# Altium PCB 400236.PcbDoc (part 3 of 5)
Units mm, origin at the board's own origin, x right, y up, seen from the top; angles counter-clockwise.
Board outline 136.53 x 63.5 mm, 4 copper layers (Top Layer, Mid-Layer 1, Mid-Layer 2, Bottom Layer), stack 1.49 mm thick; 344 components, 236 nets, 1364 pads, 1393 vias.
Unrouted connection lines stored in the file: 6.
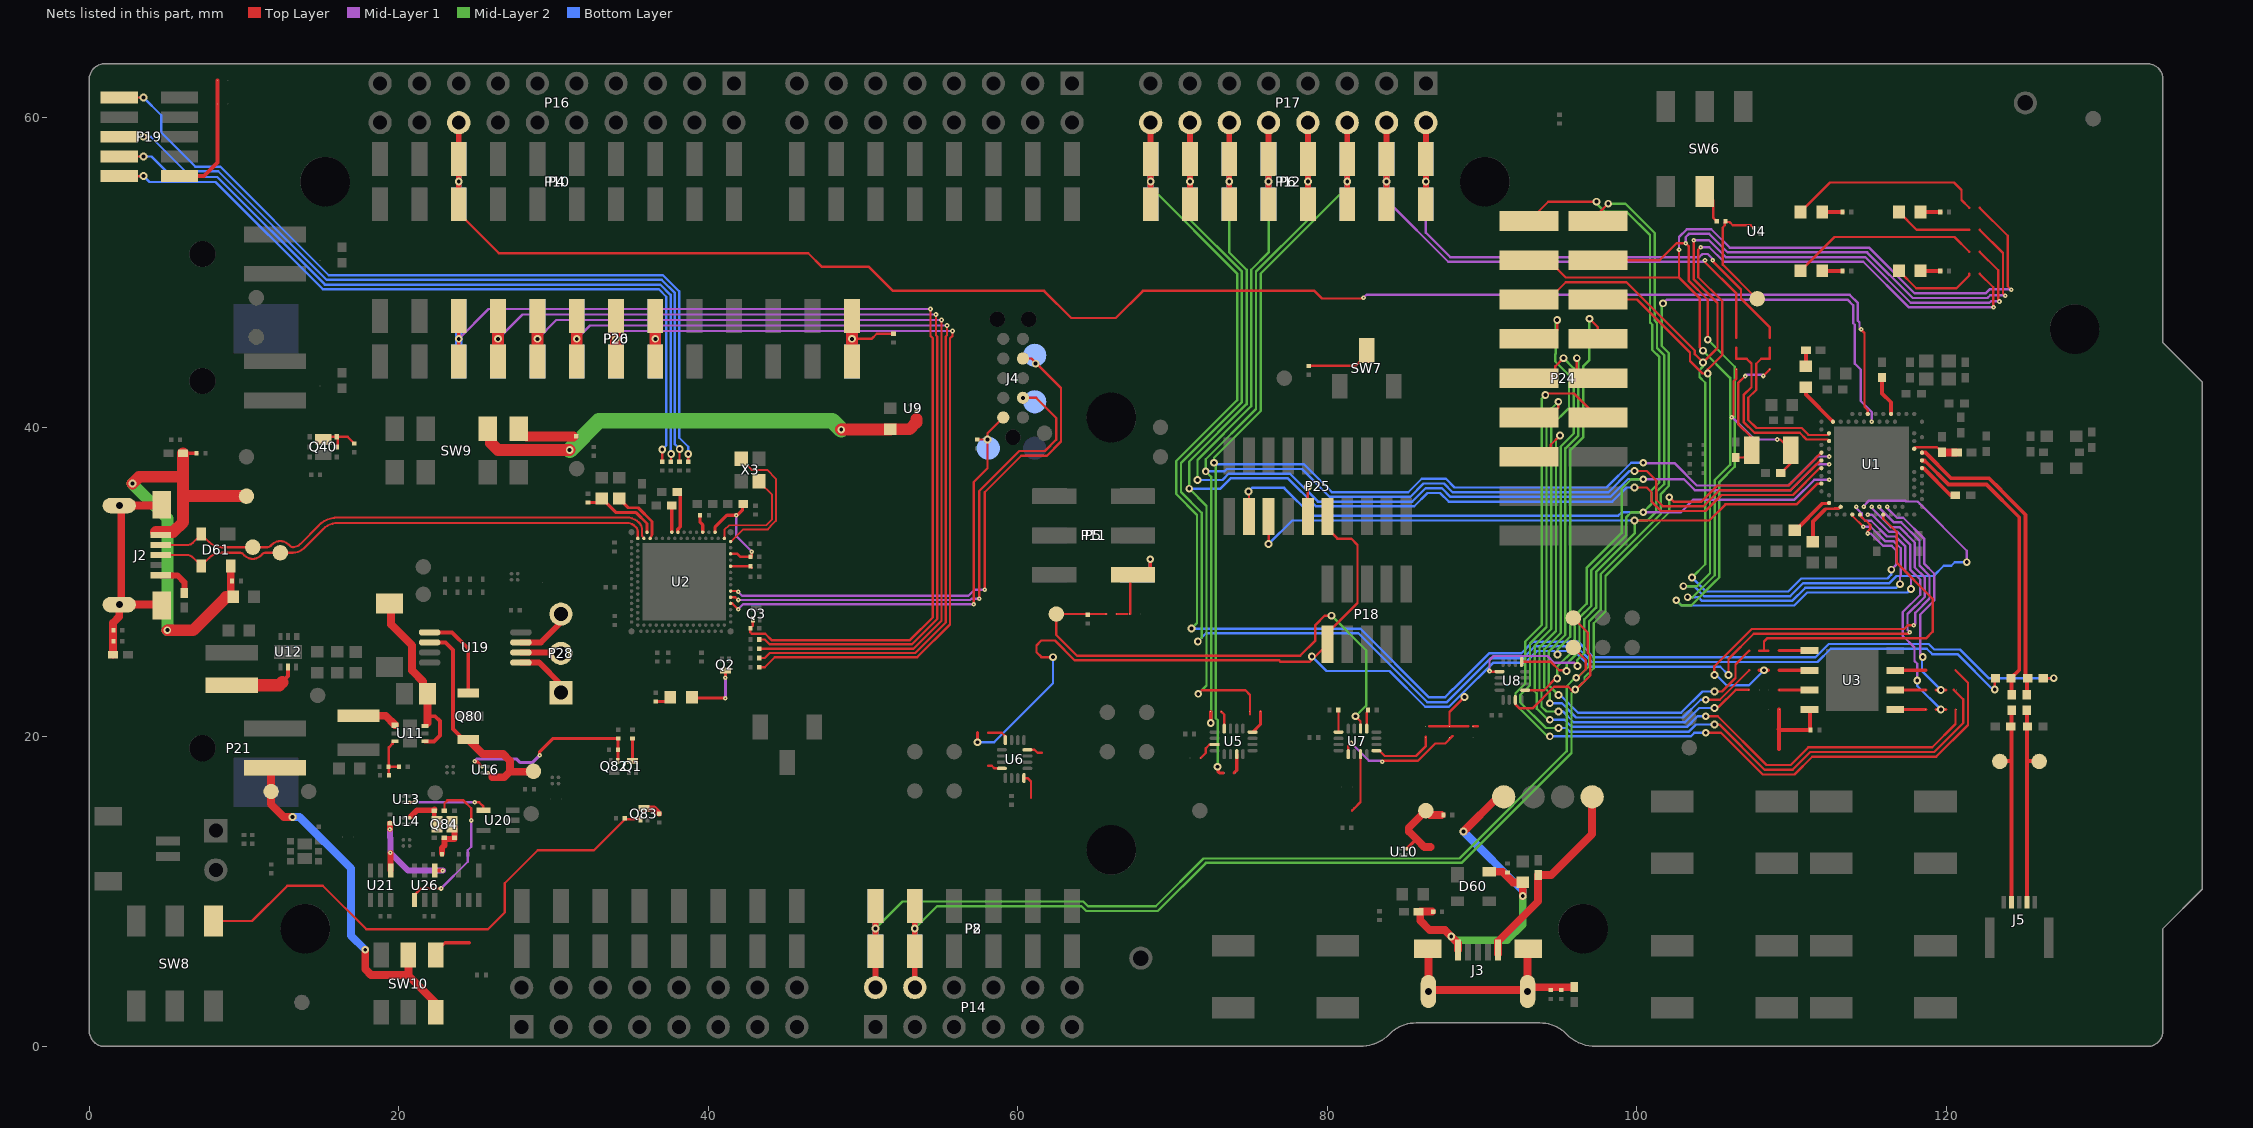
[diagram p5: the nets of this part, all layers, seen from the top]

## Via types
v1: diameter 0.5, hole 0.25, Top Layer to Bottom Layer, tented both sides, 1166 vias
v2: diameter 0.3, hole 0.1, Top Layer to Mid-Layer 1, tented top, 227 vias

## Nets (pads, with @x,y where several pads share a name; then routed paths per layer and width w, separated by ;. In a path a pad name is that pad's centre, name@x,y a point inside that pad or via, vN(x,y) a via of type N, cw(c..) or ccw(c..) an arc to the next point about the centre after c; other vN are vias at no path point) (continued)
IMCU_N: D61.2 J2.2 TP10.1 U2.B4 | length 33.6
  Top Layer w0.138: J2.2@4.619,32.398 6.34,32.398 ccw(c6.34,32.906) 6.699,32.546 D61.2@7.234,33.082 ; D61.2@7.244,33.099 7.248,33.095 7.754,32.59 ccw(c8.552,33.388) 8.552,32.259 11.506,32.259 ccw(c11.506,32.571) 11.727,32.35 11.811,32.434 cw(c12.344,31.901) 12.344,32.655 cw(c12.344,31.897) 12.88,32.433 12.964,32.349 ccw(c13.183,32.568) 13.163,32.259 ccw(c13.153,32.935) 13.631,32.457 14.84,33.666 ; 14.837,33.669 cw(c16.073,32.433) 16.063,34.181 ; U2.B4@35.839,32.827 35.839,32.877 35.714,33.002 35.714,33.379 ccw(c35.035,33.379) 35.515,33.859 ccw(c34.737,33.081) 34.737,34.181 16.073,34.181 ; 16.063,34.181 cw(c16.073,32.433) 16.073,34.181 ; 16.063,34.181 16.073,34.181
IMCU_P: D61.3 J2.3 TP9.1 U2.B2 | length 33.9
  Top Layer w0.138: J2.3@4.619,31.75 6.34,31.75 cw(c6.34,31.242) 6.699,31.601 D61.3@7.244,31.055 7.244,31.062 7.754,31.571 ; 35.275,33.6 ccw(c34.737,33.062) 34.737,33.823 16.063,33.823 ccw(c16.063,32.464) 15.112,33.435 ccw(c16.063,32.464) 15.107,33.43 15.102,33.425 13.884,32.207 cw(c13.147,32.944) 13.147,31.901 11.405,31.901 ccw(c11.405,31.589) 11.184,31.81 11.1,31.726 cw(c10.566,32.259) 10.566,31.505 cw(c10.566,32.263) 10.031,31.727 9.947,31.811 ccw(c9.728,31.592) 9.728,31.901 8.551,31.901 ; 35.276,33.6 35.344,33.532 cw(c35.115,33.303) 35.439,33.303 U2.B2@35.439,32.827 ; 7.754,31.571 cw(c8.551,30.773) 8.551,31.901 ; 7.754,31.571 cw(c8.551,30.773) 8.551,31.901
IMCU_RESET: J4.10 R8.1 TP50.1 U2.AC31 | length 29.6
  Top Layer w0.152: v2(41.925,28.25) U2.AC31@41.548,28.627 ; v2(57.15,28.575) 57.15,36.474 58.033,37.358 v1@58.033,39.218 ; R8.1@57.375,39.21 57.383,39.218 v1@58.033,39.218 ; J4.10@59.055,40.64 58.039,39.624 v1(58.039,39.218) v1@58.033,39.218 ; U2.AC31@41.548,28.627 U2.AC31@41.439,28.627 U2.AC31@41.548,28.627
  Mid-Layer 1 w0.152: v2(41.925,28.25) 42.245,28.57 57.145,28.57 v2(57.15,28.575)
IMCU_SWDCLK: J4.4 TP51.1 U2.W31 | length 36
  Top Layer w0.15: U2.W31@41.439,29.427 41.873,29.427 v2(41.925,29.375)
  Top Layer w0.152: v2(57.861,29.515) 57.861,35.814 60.219,38.172 61.874,38.172 62.786,39.084 62.786,42.547 60.884,44.45 J4.4@60.325,44.45
  Mid-Layer 1 w0.152: v2(41.925,29.375) 42.175,29.125 56.811,29.125 57.201,29.515 v2(57.861,29.515)
  other v1: 61.151,44.12
IMCU_SWDIO: J4.2 TP49.1 U2.AA31 | length 33.9
  Top Layer w0.125: U2.AA31@41.439,29.027 41.748,29.027 v2(41.925,28.85)
  Top Layer w0.15: U2.AA31@41.439,29.027 41.748,29.027
  Top Layer w0.152: v2(57.506,28.931) 57.506,35.89 60.092,38.476 61.751,38.476 62.484,39.209 62.484,40.604 61.178,41.91 v1(60.325,41.91)
  Mid-Layer 1 w0.152: v2(41.925,28.85) 41.927,28.848 56.926,28.848 57.005,28.926 57.026,28.926 57.033,28.933 57.504,28.933 v2(57.506,28.931)
N\R\F\_\O\N\L\Y\: R3.1 TP22.1 U4.B2 | length 8
  Top Layer w0.152: U4.B2@107.544,52.876 107.357,53.063 106.187,53.063 105.98,53.27 105.765,53.27 R3.1@105.72,53.315 105.676,53.27 105.676,53.055 105.537,52.916 105.537,50.516 107.743,48.311 TP22.1@107.772,48.311
NetC3_2: C3.2 L1.1 U1.H23 | length 2.9
  Top Layer w0.145: U1.H23@117.914,38.617 118.019,38.722 119.384,38.722 119.718,38.388 C3.2@119.723,38.383
  Top Layer w0.508: C3.2@119.718,38.388 L1.1@120.612,38.388
NetC9_1: C9.1 U1.N24 | length 2.9
  Top Layer w0.25: U1.N24@118.414,37.367 118.5,37.367 120.25,35.617 C9.1@120.564,35.617
NetC13_1: C13.1 U1.A18 | length 2.6
  Top Layer w0.25: C13.1@115.839,43.217 115.839,42.2 116.414,41.625 U1.A18@116.414,40.867
NetC17_2: C17.2 SB2.1 X2.1 | length 8.3
  Top Layer w0.152: C17.2@106.385,38.05 106.921,38.05 107.421,38.55 107.421,39.34 106.537,40.224 106.537,42.86 v2(106.995,43.317) ; v2@107.02,43.317 v2@107.045,43.291 ; v2(108.153,43.325) SB2.1@108.585,43.757
  Mid-Layer 1 w0.152: v2@107.104,43.401 108.077,43.401 v2(108.153,43.325)
NetC18_2: C18.2 SB1.1 X2.2 | length 9.6
  Top Layer w0.152: v2(106.121,40.665) 106.24,40.784 106.24,42.983 106.426,43.169 SB1.1@106.426,43.757 ; v2(109.068,39.218) 109.254,39.218 109.921,38.55 X2.2@109.921,38.525 109.921,37.675 C18.2@109.298,37.052
  Mid-Layer 1 w0.152: v2@106.147,40.665 107.594,39.218 v2(109.068,39.218)
NetC20_1: C20.1 U1.AC5 | length 3.6
  Top Layer w0.184: C20.1@111.354,32.614 C20.1@111.354,32.617 ; 112.062,34.608 112.202,34.747 112.254,34.747 112.258,34.743 112.749,34.743 112.755,34.749 113.045,34.749 U1.AC5@113.164,34.867
  Top Layer w0.254: C20.1@111.364,32.617 111.364,33.909 112.112,34.657
NetC29_2: C29.2 C30.1 U2.A27 U2.G31 | length 7.5
  Top Layer w0.152: U2.G31@41.439,31.827 41.875,31.827 42.05,31.652 42.804,31.652 v2(42.804,31.975)
  Top Layer w0.2: U2.A27@40.439,33.227 40.439,33.57 41.194,34.326 v2(41.814,34.326) 41.863,34.326 42.214,34.677 C29.2@42.214,35.077
  Mid-Layer 1 w0.152: v2(41.814,34.326) 41.814,32.965 v2(42.804,31.975)
NetC36_2: C36.2 U2.A15 | length 2.7
  Top Layer w0.225: C36.2@37.989,35.832 38.189,35.632 38.189,33.577 38.039,33.427 U2.A15@38.039,33.227
NetC37_1: C37.1 R13.2 U2.A5 | length 5.1
  Top Layer w0.15: U2.A5@36.039,33.227 U2.A5@36.064,33.252
  Top Layer w0.18: U2.A5@36.059,33.252 36.059,33.342
  Top Layer w0.2: R13.2@32.225,35.14 33.401,35.14 34.048,34.492 35.339,34.492 36.039,33.793 U2.A5@36.039,33.227
NetC38_1: C38.1 U2.B6 | length 3.9
  Top Layer w0.187: C38.1@34.239,35.402 34.83,34.811 35.471,34.811 36.37,33.912 36.37,33.101 ; C38.1@34.539,35.402 C38.1@34.539,35.407 ; U2.B6@36.239,32.827 36.37,33.097
NetC39_1: C39.1 U2.A23 | length 1.2
  Top Layer w0.2: C39.1@39.473,34.327 39.473,33.868 39.639,33.702 U2.A23@39.639,33.227
NetC40_2: C40.2 U2.A13 | length 1.7
  Top Layer w0.225: U2.A13@37.639,33.227 C40.2@37.639,34.925
NetC49_2: C49.2 SB16.2 SB17.2 SB18.2 U3.8 | length 6
  Top Layer w0.254: SB18.2@109.177,19.228 SB16.2@109.177,21.768 ; 109.177,20.523 109.151,20.498 109.202,20.447 C49.2@111.168,20.447 ; U3.8@111.149,21.768 111.168,21.749 C49.2@111.168,20.447 ; C49.2@111.184,20.447 C49.2@111.168,20.447
NetC53_2: C53.2 Q82.1 R5.2 U16.B2 | length 12.3
  Top Layer w0.203: v2(24.9,18.425) 24.928,18.397 25.062,18.397 U16.B2@25.378,18.082 ; v2(29.1,18.825) 29.1,19.05 29.94,19.89 R5.2@34.175,19.89 34.168,19.883 34.168,19.183 C53.2@34.16,19.175 34.155,19.17 34.155,18.455 Q82.1@34.15,18.45
  Mid-Layer 1 w0.203: v2(24.9,18.425) 25.041,18.566 27.634,18.566 27.859,18.341 28.616,18.341 v2(29.1,18.825)
NetC60_2: C60.2 C61.2 C62.2 D60.4 FB60.1 J3.1 TP15.1 | length 24.1
  Top Layer w0.508: C60.2@86.766,8.712 85.997,8.712 85.997,8.136 86.614,7.518 87.595,7.518 v1(88,7.113) 88.429,6.684 J3.1@88.429,6.232 ; v1(88.798,13.894) TP15.1@91.034,16.129 ; D60.4@90.452,11.29 91.301,11.29 91.987,10.603 C61.2@92.623,10.603 v1(92.623,9.728)
  Mid-Layer 2 w0.508: v1(88,7.113) 88.253,6.86 91.595,6.86 92.623,7.889 v1(92.623,9.728)
  Bottom Layer w0.508: v1(88.798,13.894) 92.623,10.069 v1(92.623,9.728)
NetC63_1: C63.1 C64.2 C65.2 D61.4 FB61.1 J2.1 TP11.1 | length 32.4
  Top Layer w0.254: FB61.1@6.063,38.329 C63.1@6.934,38.329
  Top Layer w0.508: C64.2@9.144,29.058 D61.4@9.144,31.055
  Top Layer w0.762: v1(2.794,36.373) 3.226,36.805 6.06,36.805 ; J2.1@4.318,33.233 5.41,33.233 6.06,33.884 6.06,35.56 ; v1(5.05,26.9) 6.707,26.9 8.846,29.039 9.291,29.039 9.297,29.045 C64.2@9.297,29.058 ; FB61.1@6.063,38.329 6.06,38.326 6.06,36.805 ; TP11.1@10.16,35.56 6.06,35.56 ; 6.06,35.56 6.06,36.805
  Mid-Layer 2 w0.762: v1(2.794,36.373) 5.05,34.117 v1(5.05,26.9)
NetC66_2: C66.2 FB64.1 J3.6@86.479,6.305 J3.6@86.529,3.557 J3.6@92.929,3.557 J3.6@92.979,6.305 R62.2 | length 14.9
  Top Layer w0.508: J3.6@86.427,3.653 J3.6@93.027,3.653 ; J3.6@86.479,6.305 86.529,6.255 J3.6@86.529,3.557 ; J3.6@92.929,3.557 92.929,6.255 J3.6@92.979,6.305 ; J3.6@93.029,3.303 J3.6@93.029,3.434 ; J3.6@93.331,3.83 FB64.1@95.942,3.83
NetC67_2: C67.2 FB65.1 J2.6@1.944,28.55 J2.6@1.944,34.95 J2.6@4.692,28.5 J2.6@4.692,35 R63.2 | length 15.1
  Top Layer w0.508: FB65.1@1.546,25.317 1.546,27.378 1.944,27.776 J2.6@1.944,28.45 ; J2.6@1.944,28.55 J2.6@4.521,28.55 ; J2.6@1.944,34.95 J2.6@4.521,34.95 ; J2.6@2.071,28.45 J2.6@2.071,35.05
NetC86_2: C86.2 D84.1 U11.4 U11.6 | length 11.7
  Top Layer w0.25: 21.856,21.184 21.857,21.182 21.871,21.168
  Top Layer w0.254: U11.4@21.701,19.718 22.284,19.718 22.657,20.091 22.657,21.031 22.352,21.336 21.857,21.336
  Top Layer w0.508: D84.1@19.507,28.618 19.507,27.268 20.862,25.914 20.862,24.288 21.561,23.589 21.561,23.08 C86.2@21.857,22.784 ; 21.857,20.906 21.857,21.182 21.857,21.336 C86.2@21.857,22.76
NetC87_1: C87.1 R82.1 R84.2 U11.3 | length 3.1
  Top Layer w0.152: R82.1@19.335,18.085 R82.1@19.36,18.085 ; C87.1@19.36,17.526 R82.1@19.36,18.085 ; U11.3@19.751,19.718 19.651,19.718 19.603,19.67 19.603,19.57 19.36,19.327 R82.1@19.36,18.085 ; R84.2@20.01,18.085 R82.1@19.36,18.085
NetC92_2: C92.2 SB81.2 SW9.7 U9.A2 | length 30.6
  Top Layer w0.26: 53.45,40.55 U9.A2@53.45,41.05
  Top Layer w0.762: SW9.7@25.749,39.906 25.968,39.687 25.968,38.978 26.414,38.532 v1(31.039,38.532) ; v1@48.576,39.863 50.282,39.863 50.301,39.863 50.35,39.863 C92.2@51.75,39.863 ; C92.2@51.769,39.875 53.004,39.875 53.45,40.321 53.45,40.55
  Mid-Layer 2 w1.016: v1(31.039,38.532) 32.94,40.433 48.009,40.433 v1(48.589,39.852)
NetFB62_1: FB62.1 J3.5 TP16.1 | length 13.2
  Top Layer w0.508: J3.5@91.029,5.978 91.029,6.803 93.614,9.387 FB62.1@93.614,11.083 94.457,11.083 97.104,13.73 TP16.1@97.104,16.129
NetFB63_1: FB63.1 J2.5 | length 2.4
  Top Layer w0.381: J2.5@4.619,30.45 4.628,30.44 5.704,30.44 6.147,29.997 FB63.1@6.147,29.304
NetL2_1: L2.1 L3.2 | length 1.1
  Top Layer w0.25: L2.1@110.914,43.942 L3.2@110.914,44.992
NetL2_2: L2.2 U1.B3 | length 2.9
  Top Layer w0.25: L2.2@110.914,42.592 110.914,42.117 U1.B3@112.664,40.367
NetL4_2: L4.2 U1.AB2 | length 3.1
  Top Layer w0.203: 111.957,35.063 111.98,35.087 112.383,35.087 U1.AB2@112.414,35.117
  Top Layer w0.25: L4.2@110.189,33.342 L4.2@110.236,33.342 ; L4.2@110.33,33.342 L4.2@110.236,33.342 ; 111.957,35.063 L4.2@110.236,33.342
NetL80_2: L80.2 U12.5 | length 3.6
  Top Layer w0.25: 12.596,23.672 12.85,23.926 U12.5@12.85,24.475
  Top Layer w0.8: L80.2@9.849,23.35 12.274,23.35 12.469,23.545
NetL81_1: L81.1 U11.1 | length 2.6
  Top Layer w0.508: L81.1@17.399,21.369 19.151,21.369 U11.1@19.751,20.768
NetLED1_1: LED1.1 SB5.2 | length 12.7
  Top Layer w0.152: LED1.1@110.575,53.917 112.48,55.822 120.479,55.822 120.965,55.337 120.965,54.696 SB5.2@121.464,54.197
NetLED1_2: LED1.2 R47.1 | length 1.3
  Top Layer w0.254: LED1.2@111.972,53.917 R47.1@113.274,53.917
NetLED2_1: LED2.1 SB6.2 | length 5
  Top Layer w0.152: LED2.1@116.925,53.917 118.067,52.774 120.968,52.774 SB6.2@121.464,52.774
NetLED2_2: LED2.2 R48.1 | length 1.3
  Top Layer w0.254: LED2.2@118.322,53.917 R48.1@119.599,53.917
NetLED3_1: LED3.1 SB7.2 | length 12.2
  Top Layer w0.152: LED3.1@110.575,50.107 112.766,52.299 120.517,52.299 SB7.2@121.464,51.352
NetLED3_2: LED3.2 R50.1 | length 1.3
  Top Layer w0.254: LED3.2@111.972,50.107 R50.1@113.274,50.107
NetLED4_1: LED4.1 SB8.2 | length 5.5
  Top Layer w0.152: LED4.1@116.925,50.107 118.042,48.99 120.643,48.99 121.464,49.81 SB8.2@121.464,49.93
NetLED4_2: LED4.2 R51.1 | length 1.3
  Top Layer w0.254: LED4.2@118.322,50.107 R51.1@119.599,50.107
NetLED5_1: LED5.1 Q2.3 | length 4
  Top Layer w0.2: LED5.1@38.938,22.575 39.002,22.51 v2@41.09,22.51 ; v2(41.1,23.825) Q2.3@41.1,24.3
  Mid-Layer 1 w0.2: v2@41.09,22.5 v2(41.1,22.51) v2(41.1,23.825)
NetLED5_2: LED5.2 R7.1 | length 1.1
  Top Layer w0.2: R7.1@36.6,22.29 37.256,22.29 LED5.2@37.541,22.575
NetP5_6: P5.6 P11.6 SB32.2 SB33.1 | length 5.2
  Top Layer w0.152: SB33.1@66.378,27.94 67.077,27.94 ; P5.6@67.119,30.48 67.252,30.348 67.252,28.293 67.252,27.94
  Top Layer w0.254: P5.6@68.555,30.531 v1(68.555,31.481)
  Bottom Layer w0.254: P11.6@68.555,30.531 v1(68.555,31.481)
NetP6_7: P6.7 P12.7 P17.14 R43.1 | length 99.3
  Top Layer w0.152: v1(123.114,23.063) 123.114,23.745 R43.1@123.169,23.8
  Top Layer w0.381: P6.7@71.12,54.415 v1(71.12,55.88) P6.7@71.12,57.345 P17.14@71.12,59.69
  Mid-Layer 2 w0.152: v1(71.12,55.88) 71.12,53.417 74.473,50.064 74.473,41.631 70.536,37.694 70.536,35.822 71.882,34.475 71.882,26.416 v1(71.628,26.162)
  Bottom Layer w0.152: v1(71.628,26.162) 72.161,26.695 82,26.695 86.445,22.25 87.729,22.25 90.571,25.092 92.648,25.092 93.413,25.857 96.073,25.857 97.089,24.841 111.658,24.841 ; 111.658,24.845 112.518,25.704 118.721,25.704 119.075,25.349 120.701,25.349 122.987,23.063 v1(123.114,23.063)
  Bottom Layer w0.381: P12.7@71.12,54.415 v1(71.12,55.88) P12.7@71.12,57.345
NetP6_8: P6.8 P12.8 P17.16 R45.1 | length 102.9
  Top Layer w0.152: R45.1@126.251,23.8 v1(126.928,23.8)
  Top Layer w0.381: P6.8@68.58,54.415 v1(68.58,55.88) P6.8@68.58,57.345 P17.16@68.58,59.69
  Mid-Layer 2 w0.152: v1(68.58,55.88) 68.58,55.526 74.168,49.938 74.168,41.758 70.231,37.821 70.231,35.695 71.577,34.349 71.577,27.356 v1(71.222,27)
  Bottom Layer w0.152: v1@71.425,27 82.126,27 86.571,22.555 87.603,22.555 87.63,22.582 87.63,22.598 88.121,23.089 88.137,23.089 90.445,25.397 92.521,25.397 93.287,26.162 96.196,26.162 97.212,25.146 111.532,25.146 112.392,26.006 118.849,26.006 119.201,25.654 120.861,25.654 122.715,23.8 v1(126.928,23.8)
  Bottom Layer w0.381: P12.8@68.58,54.415 v1(68.58,55.88) P12.8@68.58,57.345
NetP19_1: P19.1 SB19.1 SB47.2 | length 8.1
  Top Layer w0.254: P19.1@5.836,56.236 7.411,56.236 8.298,57.123 8.298,60.65 8.298,62.408
NetP19_2: P19.2 R11.2 | length 49.4
  Top Layer w0.152: P19.2@1.936,56.236 v1(3.505,56.236) ; R11.2@37.021,37.779 37.021,38.571 v1(37.025,38.575)
  Bottom Layer w0.152: v1(3.505,56.236) 3.886,55.855 8.164,55.855 15.098,48.92 36.812,48.92 37.287,48.446 37.287,38.837 v1(37.025,38.575)
NetP19_4: P19.4 R12.2 | length 50.1
  Top Layer w0.152: P19.4@1.936,57.506 v1(3.505,57.506) ; R12.2@37.579,37.779 37.59,37.79 37.59,38.265 v1(37.6,38.275)
  Bottom Layer w0.152: v1(3.505,57.506) 4.025,57.506 5.349,56.181 8.268,56.181 15.224,49.225 36.9,49.225 37.565,48.56 37.565,38.31 v1(37.6,38.275)
NetP19_6: P19.6 R14.2 | length 51.1
  Top Layer w0.152: P19.6@1.936,58.776 v1(3.505,58.776) ; R14.2@38.138,37.779 v1@38.138,38.598
  Bottom Layer w0.152: v1(3.505,58.776) 3.975,58.776 6.204,56.547 8.334,56.547 15.351,49.53 36.987,49.53 37.842,48.675 37.842,38.905 v1(38.148,38.598)
NetP19_10: P19.10 R15.2 | length 53.3
  Top Layer w0.152: P19.10@1.936,61.316 v1(3.505,61.316) ; R15.2@38.697,37.779 38.701,37.783 38.7,37.785 v1(38.7,38.275)
  Bottom Layer w0.152: v1(3.505,61.316) 4.65,60.17 4.65,59.05 6.85,56.85 8.462,56.85 15.477,49.835 37.075,49.835 38.119,48.79 38.119,39.331 38.7,38.75 v1(38.7,38.275)
NetP20_3: P20.3 P26.3 Q3.1 R20.1 | length 73.6
  Top Layer w0.152: P20.3@23.876,44.255 P20.3@23.876,47.185 ; Q3.1@42.875,27.6 42.875,27.185 R20.1@42.715,27.025 42.715,26.76 42.813,26.663 43.68,26.663 44.087,26.255 53.03,26.255 54.51,27.735 54.51,45.757 54.353,45.913 v2(54.353,47.65)
  Top Layer w0.254: P20.3@23.876,44.255 v1(23.876,45.72) P20.3@23.876,47.185
  Mid-Layer 1 w0.152: v1(23.876,45.72) 25.806,47.65 v2(54.353,47.65)
  Bottom Layer w0.508: P26.3@23.876,44.255 v1(23.876,45.72) P26.3@23.876,47.185
NetP20_4: P20.4 P26.4 R16.2 | length 66.8
  Top Layer w0.152: R16.2@43.285,26.3 43.65,26.3 43.973,25.977 53.145,25.977 54.787,27.62 54.787,45.872 54.709,45.95 v2(54.709,47.295)
  Top Layer w0.762: P20.4@26.416,44.255 v1(26.416,45.72) P20.4@26.416,47.185
  Mid-Layer 1 w0.152: v1(26.416,45.72) 27.991,47.295 v2(54.709,47.295)
  Bottom Layer w0.508: P26.4@26.416,44.255 v1(26.416,45.72) P26.4@26.416,47.185
NetP20_5: P20.5 P26.5 R17.2 | length 64.4
  Top Layer w0.152: R17.2@43.285,25.7 53.26,25.7 55.064,27.505 v2(55.064,46.939)
  Top Layer w0.762: P20.5@28.956,44.255 v1(28.956,45.72) P20.5@28.956,47.185
  Mid-Layer 1 w0.152: v1(28.956,45.72) 30.175,46.939 v2(55.064,46.939)
  Bottom Layer w0.508: P26.5@28.956,44.255 v1(28.956,45.72) P26.5@28.956,47.185
NetP20_6: P20.6 P26.6 R18.2 | length 62.4
  Top Layer w0.152: R18.2@43.285,25.1 43.65,25.1 43.973,25.423 53.375,25.423 55.342,27.39 55.342,45.872 55.42,45.95 v2(55.42,46.584)
  Top Layer w0.762: P20.6@31.496,44.255 v1(31.496,45.72) P20.6@31.496,47.185
  Mid-Layer 1 w0.152: v1(31.496,45.72) 32.36,46.584 v2(55.42,46.584)
  Bottom Layer w0.508: P26.6@31.496,44.255 v1(31.496,45.72) P26.6@31.496,47.185
NetP20_7: P20.7 P26.7 R19.2 | length 60.3
  Top Layer w0.152: R19.2@43.285,24.5 43.65,24.5 44.295,25.145 53.489,25.145 55.619,27.275 55.619,45.757 55.776,45.913 v2(55.776,46.228)
  Top Layer w0.762: P20.7@34.036,44.255 v1(34.036,45.72) P20.7@34.036,47.185
  Mid-Layer 1 w0.152: v1(34.036,45.72) 34.544,46.228 v2(55.776,46.228)
  Bottom Layer w0.508: P26.7@34.036,44.255 v1(34.036,45.72) P26.7@34.036,47.185
NetP20_8: P20.8 P26.8 | length 5.9
  Top Layer w0.762: P20.8@36.576,44.255 v1(36.576,45.72) P20.8@36.576,47.185
  Bottom Layer w0.508: P26.8@36.576,44.255 v1(36.576,45.72) P26.8@36.576,47.185
NetP20_13: P20.13 P26.13 R69.2 | length 11.6
  Top Layer w0.152: P20.13@49.276,44.255 v1(49.276,45.72) ; P20.13@49.276,47.185 v1(49.276,45.72) ; R69.2@51.968,46.056 50.882,46.056 50.546,45.72 v1(49.276,45.72)
  Top Layer w0.762: P20.13@49.276,44.255 v1(49.276,45.72) P20.13@49.276,47.185
  Bottom Layer w0.508: P26.13@49.276,44.255 v1(49.276,45.72) P26.13@49.276,47.185
NetP21_2: P21.2 SW10.2 SW10.4 TP27.1 | length 23.5
  Top Layer w0.508: P21.2@11.811,18.009 11.75,17.948 TP27.1@11.75,16.475 11.75,15.65 12.566,14.834 v1(13.132,14.834) ; v1(17.831,6.248) 17.831,5.004 18.212,4.623 20.574,4.623 ; SW10.2@20.625,5.914 20.625,4.674 20.574,4.623 ; SW10.4@22.375,2.214 22.375,2.822 20.574,4.623
  Bottom Layer w0.508: v1(13.132,14.834) 13.591,14.834 16.916,11.509 16.916,7.163 v1(17.831,6.248)
NetP24_7: P24.7 SB23.2 | length 60.4
  Top Layer w0.152: P24.7@93.027,45.72 94.285,45.72 94.844,46.279 v1(94.844,46.939) ; v1(104.445,21.336) 105.225,21.336 108.374,18.186 109.932,18.186 111.075,19.329 119.076,19.329 120.581,20.835 120.581,21.768
  Mid-Layer 2 w0.152: v1(94.369,21.107) 94.251,21.107 93.531,21.827 93.531,22.811 93.396,22.947 93.396,25.909 94.463,26.976 94.463,40.107 95.606,41.25 95.606,43.365 94.717,44.254 94.717,44.722 94.742,44.747 94.742,46.838 v1(94.844,46.939)
  Bottom Layer w0.152: v1(94.369,21.107) 95.327,21.107 95.784,20.65 103.231,20.65 103.917,21.336 v1(104.445,21.336)
NetP24_9: P24.9 SB21.2 | length 40.9
  Top Layer w0.152: P24.9@93.027,43.18 94.17,43.18 94.729,43.739 94.729,43.954 v1(95.25,44.475) ; v1(104.445,22.403) 105.352,22.403 107.257,24.308
  Mid-Layer 2 w0.152: v1(94.369,22.174) 94.369,22.835 94.005,23.199 94.005,25.656 95.072,26.723 95.072,38.768 95.91,39.606 95.91,43.815 v1(95.25,44.475)
  Bottom Layer w0.152: v1(94.369,22.174) 95.149,22.174 96.064,21.26 102.979,21.26 104.122,22.403 v1(104.445,22.403)
NetP24_10: P24.10 SB22.2 | length 40.2
  Top Layer w0.152: v1(96.114,44.475) 96.114,43.739 96.672,43.18 P24.10@97.472,43.18 ; v1(105.004,22.936) 105.493,22.936 106.369,23.813 106.369,24.69 107.257,25.578
  Mid-Layer 2 w0.152: v1(94.928,22.708) 94.31,23.326 94.31,25.53 95.377,26.597 95.377,38.642 96.215,39.48 96.215,44.374 v1(96.114,44.475)
  Bottom Layer w0.152: v1(94.928,22.708) 95.047,22.708 96.19,21.565 102.852,21.565 104.224,22.936 v1(105.004,22.936)
NetP24_11: P24.11 SB24.2 | length 57.4
  Top Layer w0.152: P24.11@93.027,40.64 94.297,40.64 94.916,41.258 94.916,41.652 v1(94.92,41.656) ; v1(105.004,20.803) 105.327,20.803 108.248,17.882 110.058,17.882 111.201,19.025 119.202,19.025 121.085,20.907 121.085,22.425 120.472,23.038
  Mid-Layer 2 w0.152: v1(94.92,41.656) 94.158,40.894 94.158,27.102 93.091,26.035 93.091,23.335 92.456,22.7 92.456,22.233 94.115,20.574 v1(94.928,20.574)
  Bottom Layer w0.152: v1(94.928,20.574) 95.429,20.574 95.658,20.345 103.357,20.345 103.814,20.803 v1(105.004,20.803)
NetP24_12: P24.12 SB25.2 | length 61.3
  Top Layer w0.152: v1(94.082,42.088) 94.183,42.189 95.923,42.189 P24.12@97.472,40.64 ; v1(104.445,20.269) 105.429,20.269 108.122,17.577 110.184,17.577 111.327,18.72 119.329,18.72 121.389,20.78 121.389,23.5 120.581,24.308
  Mid-Layer 2 w0.152: v1(94.082,42.088) 93.853,41.859 93.853,27.229 92.786,26.162 92.786,23.461 92.151,22.826 92.151,22.106 94.217,20.041 v1(94.369,20.041)
  Bottom Layer w0.152: v1(94.369,20.041) 103.484,20.041 103.712,20.269 v1(104.445,20.269)
NetP24_13: P24.13 SB20.2 | length 35.5
  Top Layer w0.152: P24.13@93.027,38.1 93.865,38.1 94.424,38.659 94.424,38.874 v1(95.021,39.472) ; v1(105.004,21.869) 105.07,21.936 105.277,21.936 106.379,23.038 SB20.2@107.219,23.038
  Mid-Layer 2 w0.152: v1(94.928,21.641) 94.148,21.641 93.836,21.953 93.836,22.938 93.701,23.073 93.701,25.782 94.767,26.849 94.767,39.218 v1(95.021,39.472)
  Bottom Layer w0.152: v1(94.928,21.641) 95.225,21.641 95.91,20.955 103.105,20.955 104.019,21.869 v1(105.004,21.869)
NetP28_1: P28.1 U19.5 | length 3.7
  Top Layer w0.381: U19.5@27.893,24.806 29.067,24.806 30.48,23.393 P28.1@30.48,22.86
NetP28_2: P28.2 U19.6 | length 2.6
  Top Layer w0.381: U19.6@27.893,25.456 30.424,25.456 P28.2@30.48,25.4
NetP28_3: P28.3 U19.7 | length 3.7
  Top Layer w0.381: U19.7@27.893,26.106 29.179,26.106 30.48,27.407 P28.3@30.48,27.94
NetQ1_3: Q1.3 R6.1 | length 1.4
  Top Layer w0.203: Q1.3@35.1,18.45 R6.1@35.1,19.89
NetQ40_5: Q40.5 Q40.6 R41.2 | length 2.9
  Top Layer w0.152: Q40.6@15.113,39.21 15.288,39.385 Q40.6@16.058,39.385 ; Q40.5@16.063,38.735 16.063,39.385 16.704,39.385 17.046,39.043 17.046,39.028 17.105,38.969 R41.2@17.12,38.969
NetQ80_1: Q80.1 U19.1 | length 5.6
  Top Layer w0.254: U19.1@22.196,26.756 23.434,26.756 24.489,25.701 Q80.1@24.489,22.836
NetQ80_3: Q80.3 TP34.1 U16.A1 U19.2 | length 15
  Top Layer w0.25: U16.A1@25.778,17.682 26.065,17.394
  Top Layer w0.254: U19.2@22.196,26.106 23.018,26.106 23.51,25.614 23.51,20.509 24.182,19.836 Q80.3@24.489,19.836
  Top Layer w0.508: Q80.3@24.489,19.836 25.427,18.898 26.746,18.898 27.178,18.466 27.178,17.755 ; 26.065,17.394 26.818,17.394 27.178,17.755 ; TP34.1@28.651,17.856 28.55,17.755 27.178,17.755
NetQ83_1: Q83.1 R94.1 SW8.4 | length 33.7
  Top Layer w0.152: SW8.4@8.028,8.109 10.522,8.109 12.802,10.389 15.088,10.389 17.907,7.569 25.756,7.569 26.851,8.664 26.851,10.544 28.981,12.675 32.604,12.675 34.616,14.687 Q83.1@35.614,14.687
NetQ83_3: Q83.3 R93.2 | length 1.1
  Top Layer w0.381: Q83.3@35.839,15.387 36.486,15.387 R93.2@36.83,15.042
NetQ84_2: Q84.2 U26.4 | length 10.6
  Top Layer w0.152: U26.4@21.016,9.464 21.016,9.789 21.438,10.211 v2(22.733,10.211) ; Q84.2@22.951,15.301 22.951,15.712 23.139,15.9 24.181,15.9 24.689,15.392 v2(24.689,14.605)
  Mid-Layer 1 w0.152: v2(22.733,10.211) 24.46,11.938 24.46,12.675 24.689,12.903 v2(24.689,14.605)
NetQ84_3: Q84.3 U14.A2 | length 2.7
  Top Layer w0.305: Q84.3@22.301,15.301 22.301,14.531 Q84.3@22.476,14.356
  Top Layer w0.381: U14.A2@20.764,14.846 21.184,15.265 22.265,15.265 Q84.3@22.301,15.301
NetQ84_5: Q84.5 Q84.6 R96.2 | length 2.7
  Top Layer w0.381: R96.2@22.789,12.471 22.789,12.833 22.951,12.994 22.951,13.411 23.601,13.411 23.601,14.181 Q84.6@23.426,14.356
NetR3_2: R3.2 SW6.5 | length 2.3
  Top Layer w0.152: SW6.5@104.369,55.238 104.935,54.671 104.935,53.53 105.077,53.388 105.092,53.388 105.15,53.33 R3.2@105.15,53.315
NetR4_2: R4.2 SW7.2 | length 4.3
  Top Layer w0.152: R4.2@78.791,43.973 78.811,43.994 81.84,43.994 82.55,44.704 SW7.2@82.55,44.965
NetR9_1: R9.1 U2.L31 | length 1.4
  Top Layer w0.152: U2.L31@41.439,31.027 42.718,31.027 R9.1@42.804,30.941
NetR52_2: R52.2 U7.9 | length 1.2
  Top Layer w0.152: U7.9@82.54,20.535 82.54,21.579 82.562,21.601 82.562,21.684 R52.2@82.621,21.742
NetR53_2: R53.2 U7.13 | length 1.5
  Top Layer w0.152: R53.2@80.701,21.742 R53.2@80.715,21.728 ; U7.13@80.715,20.31 R53.2@80.715,21.728 ; R53.2@80.715,21.768 R53.2@80.715,21.728
NetR68_1: R68.1 SB33.2 TP19.1 U7.10 | length 33.2
  Top Layer w0.152: SB33.2@65.702,27.94 64.524,27.94 64.516,27.932 64.508,27.94 TP19.1@62.484,27.94 62.484,26.594 63.828,25.25 78.234,25.25 79.223,26.238 79.223,27.229 79.832,27.838 v1(80.264,27.838) ; v1(81.813,21.336) 82.14,21.009 U7.10@82.14,20.535
  Mid-Layer 2 w0.152: v1(80.264,27.838) 82.499,25.604 82.499,22.021 v1(81.813,21.336)
NetR95_2: R95.2 U21.1 U26.1 | length 7.5
  Top Layer w0.254: v2(19.456,12.522) v2@19.471,12.507 ; U26.1@22.316,11.364 v2(22.85,11.364)
  Top Layer w0.381: v2(19.431,14.046) R95.2@19.431,14.422 ; U21.1@19.471,11.364 v2@19.471,12.507
  Mid-Layer 1 w0.381: v2(19.431,14.046) 19.431,13.502 19.456,13.476 v2(19.456,12.522) 20.615,11.364 v2(22.85,11.364)
NetR97_2: R97.2 SW9.8 | length 3.7
  Top Layer w0.635: SW9.8@27.749,39.906 28.235,39.421 31.293,39.421
NetR98_1: R98.1 SB80.1 TP38.1 U10.A1 | length 5.6
  Top Layer w0.2: 85.7,13.35 85.725,13.35 85.763,13.388
  Top Layer w0.203: U10.A1@85.125,12.775 85.7,13.35
  Top Layer w0.508: TP38.1@86.614,14.986 TP38.1@86.36,15.24 85.253,14.133 85.253,13.898 85.763,13.388 86.272,12.878 86.656,12.878 ; TP38.1@86.639,14.961 R98.1@87.376,14.961
NetSB10_2: SB10.2 U3.7 | length 2
  Top Layer w0.203: SB10.2@109.177,23.038 U3.7@111.149,23.038
NetSB11_2: SB11.2 U3.6 | length 2
  Top Layer w0.203: SB11.2@109.177,24.308 U3.6@111.149,24.308
NetSB12_2: SB12.2 U3.5 | length 2
  Top Layer w0.203: SB12.2@109.177,25.578 U3.5@111.149,25.578
NetSB13_2: SB13.2 U3.1 | length 2
  Top Layer w0.203: U3.1@116.689,21.768 SB13.2@118.661,21.768
NetSB14_2: SB14.2 U3.2 | length 2
  Top Layer w0.203: U3.2@116.689,23.038 SB14.2@118.661,23.038
NetSB15_2: SB15.2 U3.3 | length 2
  Top Layer w0.203: U3.3@116.689,24.308 SB15.2@118.661,24.308
NetSB42_1: SB42.1 U7.1 | length 8.6
  Top Layer w0.152: U7.1@81.34,18.885 81.34,19.415 v2(81.534,19.609) ; v2(83.541,18.39) 83.617,18.466 85.851,18.466 86.965,19.58 87.608,19.58 88.087,20.058
  Mid-Layer 1 w0.152: v2(81.534,19.609) 82.677,18.466 83.464,18.466 v2(83.541,18.39)
NetSB45_1: SB45.1 U7.5 | length 4.2
  Top Layer w0.152: U7.5@83.165,19.11 83.361,19.11 83.701,18.771 85.725,18.771 86.36,19.406 86.36,19.833 86.36,20.008
NetSB46_1: SB46.1 U7.3 | length 3.9
  Top Layer w0.152: 81.592,15.24 81.741,15.389 82.14,15.788 U7.3@82.14,18.885
NetSB50_2: SB50.2 U5.15 | length 1.4
  Top Layer w0.125: U5.15@72.696,19.492 U5.15@72.714,19.51
  Top Layer w0.152: SB50.2@71.813,18.644 72.137,18.968 72.137,19.262 72.367,19.492 U5.15@72.696,19.492
NetSB51_2: SB51.2 U5.3 | length 1.3
  Top Layer w0.203: 73.963,17.675 74.139,17.852 U5.3@74.139,18.885
NetSB52_2: SB52.2 U5.8 | length 1.6
  Top Layer w0.152: U5.8@75.157,20.307 U5.8@75.164,20.314
  Top Layer w0.203: U5.8@75.164,20.31 75.164,20.314 75.674,20.824 SB52.2@75.674,21.641
NetSB53_2: SB53.2 U5.12 | length 1.2
  Top Layer w0.152: SB53.2@73.134,21.641 73.332,21.443 U5.12@73.332,20.532
NetSB54_2: SB54.2 U6.16 | length 1.6
  Top Layer w0.152: U6.16@60.392,17.342 60.628,17.342 60.851,17.119 SB54.2@60.851,16.078
NetSB55_2: SB55.2 U6.4 | length 1
  Top Layer w0.152: U6.4@60.617,19.167 61.071,19.167 61.265,18.974 SB55.2@61.562,18.974
NetSB56_2: SB56.2 U6.8 | length 1.5
  Top Layer w0.152: SB56.2@58.072,20.269 58.953,20.269 59.192,20.031 U6.8@59.192,19.792
NetSB57_2: SB57.2 U6.12 | length 1
  Top Layer w0.152: SB57.2@58.072,18.136 58.318,18.136 58.487,17.967 U6.12@58.967,17.967 U6.12@58.967,17.937
NetSB58_2: SB58.2 SW10.1 | length 2.6
  Top Layer w0.203: SW10.1@22.375,5.914 22.375,6.093 22.987,6.706 SB58.2@24.58,6.706
NetU2_B30: U2.B30 X3.3 | length 6.7
  Top Layer w0.125: U2.B30@41.039,32.827 41.039,33.375 41.341,33.677 43.735,33.677 44.117,34.058 44.117,35.633 43.312,36.438 X3.3@43.275,36.475
NetU2_C31: U2.C31 X3.1 | length 9
  Top Layer w0.125: U2.C31@41.439,32.627 41.463,32.627 42.251,33.414 43.846,33.414 44.016,33.584 44.016,33.604 44.367,33.955 44.367,36.683 43.8,37.25 42.8,37.25 42.125,37.925 X3.1@42.125,37.975
NetU13_B2: U13.B2 U20.4 | length 5.1
  Top Layer w0.152: U13.B2@20.698,15.777 20.699,15.775 21.033,15.775 v2(21.034,15.774) ; v2(24.917,15.774) 24.92,15.777 25.194,15.777 25.466,15.504 U20.4@25.466,15.255
  Mid-Layer 1 w0.152: v2(21.034,15.774) v2(24.917,15.774)
NFC1: C46.1 J5.2 R44.1 TP17.1 | length 12.9
  Top Layer w0.25: TP17.1@123.479,18.44 124.198,18.44 ; J5.2@124.198,9.328 124.198,18.44 ; R44.1@124.198,21.463 124.198,18.44
NFC2: C47.2 J5.4 R46.1 TP18.1 | length 12.8
  Top Layer w0.25: J5.4@125.198,9.328 125.198,18.44 ; R46.1@125.198,21.463 125.198,18.44 ; TP18.1@125.909,18.44 125.198,18.44
P0.00: P6.1 P12.1 P17.2 SB4.2 | length 37.6
  Top Layer w0.152: v2@104.851,50.775 106.723,48.902 106.723,48.318 108.585,46.457 108.585,45.953 108.585,45.778
  Top Layer w0.381: P6.1@86.36,54.415 v1(86.36,55.88) P6.1@86.36,57.345 P17.2@86.36,59.69
  Mid-Layer 1 w0.152: v1(86.36,55.88) 86.36,52.577 87.934,51.003 104.026,51.003 104.227,51.204 104.578,51.204 104.902,50.879 v2(104.902,50.8) ; v2@104.851,50.775 v2@104.851,50.8
  Bottom Layer w0.381: P12.1@86.36,54.415 v1(86.36,55.88) P12.1@86.36,57.345
P0.00/XL1: SB2.2 SB4.1 U1.D2 | length 11.2
  Top Layer w0.145: 111.1,39.512 112.309,39.512 U1.D2@112.414,39.617
  Top Layer w0.152: 108.585,45.154 108.585,44.432 108.029,44.432 107.703,44.107 107.703,42.418 107.195,41.91 107.195,40.479 107.716,39.958 110.642,39.958 111.077,39.523
P0.01: P6.2 P12.2 P17.4 SB3.2 | length 37.4
  Top Layer w0.152: v2(104.394,50.8) 104.394,50.673 106.426,48.641 106.426,45.953 106.426,45.778
  Top Layer w0.381: P6.2@83.82,54.415 v1(83.82,55.88) P6.2@83.82,57.345 P17.4@83.82,59.69
  Mid-Layer 1 w0.152: v1(83.82,55.88) 83.82,54.686 87.808,50.698 v2@104.318,50.698
  Bottom Layer w0.381: P12.2@83.82,54.415 v1(83.82,55.88) P12.2@83.82,57.345
P0.01/XL2: SB1.2 SB3.1 U1.F2 | length 11.9
  Top Layer w0.145: 110.922,39.222 112.309,39.222 U1.F2@112.414,39.117
  Top Layer w0.152: 106.426,45.154 106.426,44.432 107.086,44.432 107.399,44.12 107.399,42.596 106.891,42.088 106.891,40.353 107.59,39.654 110.516,39.654 110.922,39.248 110.922,39.222
P0.02/AIN0: P4.8 P10.8 P16.16 U1.A12 | length 111.2
  Top Layer w0.152: P4.8@23.876,54.415 23.876,53.848 26.467,51.257 46.455,51.257 47.344,50.368 50.375,50.368 51.924,48.819 61.694,48.819 63.447,47.066 66.326,47.066 68.079,48.819 79.164,48.819 79.65,48.332 82.289,48.332 v2(82.333,48.376) ; v2(114.478,46.33) 114.702,46.106 114.702,41.33 114.914,41.119 U1.A12@114.914,40.867
  Top Layer w0.381: P4.8@23.876,54.415 v1(23.876,55.88) P4.8@23.876,57.345 P16.16@23.876,59.69
  Mid-Layer 1 w0.152: v2(82.333,48.376) 82.522,48.565 113.741,48.565 114.275,48.031 114.275,46.886 114.374,46.786 114.374,46.434 v2(114.478,46.33)
  Bottom Layer w0.381: P10.8@23.876,53.848 v1(23.876,55.88) P10.8@23.876,57.345
P0.03/AIN1: P2.1 P8.1 P14.2 TP42.1 U1.B13 | length 113.6
  Top Layer w0.152: TP42.1@95.885,25.781 96.69,24.976 96.69,24.369 96.146,23.825 v1(96.081,23.825)
  Top Layer w0.381: P14.2@50.8,3.81 P2.1@50.8,6.155 v1(50.8,7.62) P2.1@50.8,9.085
  Mid-Layer 1 w0.152: v1(101.676,48.014) 101.92,48.258 113.592,48.258 113.97,47.88 113.97,46.724 114.071,46.622 114.071,44.119 114.456,43.735 114.456,41.706 115.164,40.998 v2(115.164,40.367)
  Mid-Layer 2 w0.152: v1(50.8,7.62) 52.553,9.373 64.226,9.373 64.541,9.057 68.912,9.057 72.003,12.149 88.527,12.149 95.462,19.084 95.462,23.275 95.974,23.787 96.119,23.787 96.901,24.569 96.901,27.467 97.663,28.229 97.663,30.532 101.244,34.113 101.244,34.116 101.542,34.414 101.542,35.687 101.552,35.697 101.552,35.704 102.057,36.209 102.057,44.799 101.6,45.256 101.6,47.937 v1(101.676,48.014)
  Bottom Layer w0.381: P8.1@50.8,6.155 v1(50.8,7.62) P8.1@50.8,9.677
P0.04/AIN2: P2.2 P8.2 P14.4 TP43.1 U1.J1 U8.15 | length 96.4
  Top Layer w0.15: U1.J1@111.86,38.319 U1.J1@111.908,38.367
  Top Layer w0.152: U8.15@92.148,22.397 92.148,22.101 92.406,21.843 93.243,21.843 94.64,23.241 95.555,23.241 v1@95.872,22.924 ; TP43.1@95.885,27.686 96.825,26.746 96.825,25.425 96.988,25.262 96.988,23.989 v1@96.037,23.038 ; v1(102.083,35.484) 102.362,35.204 104.168,35.204 105.209,36.246 109.8,36.246 109.979,36.424 109.979,36.426 111.547,37.995 111.547,38.019 111.762,38.233 111.786,38.233 111.86,38.307 U1.J1@111.86,38.319 ; U1.J1@111.908,38.367 U1.J1@111.914,38.367
  Top Layer w0.381: P14.4@53.34,3.81 P2.2@53.34,6.155 v1(53.34,7.62) P2.2@53.34,9.085
  Mid-Layer 2 w0.152: v1(53.34,7.62) 54.788,9.068 64.1,9.068 64.415,8.753 69.038,8.753 72.147,11.862 73.33,11.862 88.671,11.862 95.766,18.957 95.766,22.818 v1(96.012,23.063) ; v1@96.041,23.034 96.612,23.606 96.612,23.853 97.203,24.444 97.203,25.017 97.206,25.019 97.206,27.341 97.968,28.103 97.968,30.405 102.083,34.52 v1(102.083,35.484)
  Bottom Layer w0.381: P8.2@53.34,6.155 v1(53.34,7.62) P8.2@53.34,9.085
P0.05/AIN3: P6.3 P12.3 P17.6 SB51.1 U1.K2 | length 93.4
  Top Layer w0.203: v1@72.8,18.075 v1@72.857,18.018 ; v1(72.9,18.075) 72.947,18.028 72.947,17.744 73.016,17.675 73.213,17.675 73.287,17.675
  Top Layer w0.381: P6.3@81.28,54.661 v1(81.28,55.88) P6.3@81.28,57.345 P17.6@81.28,59.69
  Mid-Layer 1 w0.152: v1@100.432,37.694 102.417,37.694 103.865,36.246 109.8,36.246 111.672,38.117 v2(112.414,38.117)
  Mid-Layer 2 w0.152: v1(72.9,18.075) 72.91,18.085 72.91,21.083 72.796,21.197 72.796,37.498 72.669,37.625 72.669,38.042 75.692,41.065 75.692,49.936 81.28,55.524 v1(81.28,55.88)
  Bottom Layer w0.152: v1(72.669,37.719) 72.771,37.617 78.486,37.617 80.289,35.814 85.227,35.814 86.091,36.678 87.655,36.678 88.214,36.119 98.026,36.119 99.626,37.719 v1(100.406,37.719)
  Bottom Layer w0.381: P12.3@81.28,54.415 v1(81.28,55.88) P12.3@81.28,57.345
P0.06: P6.4 P12.4 P17.8 SB53.1 U1.L1 | length 91.5
  Top Layer w0.15: 109.804,35.941 109.925,35.941 110.282,36.299 110.282,36.3 111.85,37.867 U1.L1@111.914,37.867
  Top Layer w0.152: v1(99.847,37.186) 100.627,37.186 101.244,36.568 101.244,35.33 101.675,34.9 104.294,34.9 105.335,35.941 109.804,35.941
  Top Layer w0.203: v1(72.459,20.897) 72.459,21.288 SB53.1@72.459,21.641
  Top Layer w0.381: P6.4@78.74,54.415 v1(78.74,55.88) P6.4@78.74,57.345 P17.8@78.74,59.69
  Mid-Layer 2 w0.152: v1(72.459,20.897) 72.492,20.93 72.492,36.805 v1(72.136,37.16) 72.136,37.94 75.387,41.191 75.387,50.063 78.74,53.415 v1(78.74,55.88)
  Bottom Layer w0.152: v1(72.136,37.16) 73.339,37.16 73.491,37.313 78.351,37.313 80.155,35.509 85.353,35.509 86.217,36.373 87.529,36.373 88.088,35.814 98.153,35.814 99.524,37.186 v1(99.847,37.186)
  Bottom Layer w0.381: P12.4@78.74,54.415 v1(78.74,55.88) P12.4@78.74,57.345
P0.07: P6.5 P12.5 P17.10 P25.12 U1.M2 U8.1 | length 92.9
  Top Layer w0.152: P25.12@78.74,34.245 v1(78.74,36.17) ; U8.1@92.773,23.022 93.99,23.022 94.743,23.774 v1(94.844,23.774)
  Top Layer w0.381: P6.5@76.2,54.61 v1(76.2,55.88) P6.5@76.2,57.345 P17.10@76.2,59.69
  Mid-Layer 1 w0.152: v1(100.406,36.652) 103.031,36.652 103.742,35.941 109.927,35.941 111.603,37.617 v2(112.414,37.617)
  Mid-Layer 2 w0.152: v1(71.603,36.601) 71.603,37.897 75.082,41.377 75.082,50.189 76.2,51.306 v1(76.2,55.88) ; v1(94.844,23.774) 94.844,24.544 95.987,25.687 95.987,27.846 96.749,28.608 96.749,30.91 99.009,33.171 99.009,36.035 99.626,36.652 v1(100.406,36.652)
  Bottom Layer w0.152: v1(71.603,36.601) 73.211,36.601 73.618,37.008 77.579,37.008 79.382,35.204 85.479,35.204 86.343,36.068 87.403,36.068 87.962,35.509 98.279,35.509 99.422,36.652 v1(100.406,36.652)
  Bottom Layer w0.381: P12.5@76.2,54.415 v1(76.2,55.88) P12.5@76.2,57.345
P0.08: P6.6 P12.6 P17.12 SB52.1 U1.N1 | length 93.5
  Top Layer w0.15: 110.082,35.636 111.814,37.367 U1.N1@111.914,37.367
  Top Layer w0.152: v1(71.653,22.784) 71.884,23.014 74.7,23.014 74.999,22.716 74.999,21.463 ; v1(99.847,36.119) 100.627,36.119 100.94,35.806 100.94,35.204 101.548,34.595 104.42,34.595 105.462,35.636 110.082,35.636
  Top Layer w0.381: P6.6@73.66,54.712 v1(73.66,55.88) P6.6@73.66,57.345 P17.12@73.66,59.69
  Mid-Layer 2 w0.152: v1(71.653,22.784) 72.187,23.317 72.187,34.925 v1(71.069,36.043) 71.069,37.794 74.778,41.503 74.778,50.19 73.66,51.308 v1(73.66,55.88)
  Bottom Layer w0.152: v1(71.069,36.043) 73.083,36.043 73.744,36.703 77.452,36.703 79.256,34.9 85.606,34.9 86.469,35.763 87.277,35.763 87.835,35.204 98.405,35.204 99.319,36.119 v1(99.847,36.119)
  Bottom Layer w0.381: P12.6@73.66,54.415 v1(73.66,55.88) P12.6@73.66,57.345
P0.09/NFC1: R43.2 R44.2 U1.L24 | length 19.6
  Top Layer w0.25: U1.L24@118.414,37.867 118.569,37.867 118.569,37.782 118.655,37.782 120.125,36.311 122.585,36.311 124.699,34.197 124.699,24.33 R43.2@124.169,23.8 124.206,23.762 R44.2@124.206,22.725
P0.10/NFC2: R45.2 R46.2 U1.J24 | length 20
  Top Layer w0.25: U1.J24@118.414,38.367 118.638,38.367 120.292,36.714 122.751,36.714 123.484,35.981 123.484,35.971 125.101,34.354 125.101,23.95 R45.2@125.251,23.8 ; R46.2@125.197,22.725 R45.2@125.197,23.745
P0.11: P24.1 P25.18 U1.T2 U8.5 | length 84.7
  Top Layer w0.152: v1(74.905,35.865) 74.93,35.839 P25.18@74.93,34.245 ; U8.5@92.548,24.847 94.437,24.847 94.976,24.308 95.402,24.308 v1(95.453,24.257) ; P24.1@93.027,53.34 94.272,54.585 v1(97.384,54.585)
  Mid-Layer 1 w0.152: v1(100.406,34.519) 102.84,34.519 103.653,35.331 110.179,35.331 111.465,36.617 v2(112.414,36.617)
  Mid-Layer 2 w0.152: v1(95.453,24.257) 95.453,24.714 96.291,25.552 96.291,27.72 97.053,28.482 97.053,30.784 99.314,33.045 99.314,34.206 99.626,34.519 v1(100.406,34.519) 100.937,35.05 100.937,35.945 101.448,36.455 101.448,44.547 100.99,45.004 100.99,46.627 100.838,46.78 100.838,52.426 99.34,53.924 97.925,53.924 97.384,54.465 v1(97.384,54.585)
  Bottom Layer w0.152: v1(74.905,35.865) 75.133,36.093 77.2,36.093 79.003,34.29 98.784,34.29 99.012,34.519 v1(100.406,34.519)
P0.12: P24.2 P25.16 U1.U1 U8.9 | length 82.8
  Top Layer w0.15: 110.16,35.027 110.315,35.027 111.656,36.367 U1.U1@111.914,36.367
  Top Layer w0.152: v1(76.2,32.461) P25.16@76.2,34.245 ; v2(90.475,24.257) 90.51,24.222 U8.9@91.123,24.222 ; P24.2@97.472,53.34 97.472,53.784 v1(98.146,54.458) ; v1(99.847,33.985) 104.673,33.985 105.714,35.027 110.16,35.027
  Mid-Layer 1 w0.152: v2(90.475,24.257) 90.475,24.97 90.73,25.226 94.213,25.226 94.648,24.79 95.961,24.79 v1(96.164,24.587)
  Mid-Layer 2 w0.152: v1@96.139,24.587 96.139,24.969 96.596,25.426 96.596,27.594 97.358,28.356 97.358,30.658 99.847,33.147 v1(99.847,33.985) 100.686,33.985 101.24,34.539 101.24,35.819 101.752,36.332 101.752,44.673 101.295,45.13 101.295,46.754 101.143,46.906 101.143,52.553 99.238,54.458 v1(98.146,54.458)
  Bottom Layer w0.152: v1(76.2,32.461) 77.724,33.985 v1(99.847,33.985)
P0.13: P24.3 SB5.1 U1.AD8 | length 86
  Top Layer w0.152: P24.3@93.497,50.8 94.285,50.8 95.402,49.682 102.718,49.682 ; v2(102.718,51.486) 102.718,49.682 ; v1(104.267,44.958) 104.046,45.179 104.046,48.354 102.718,49.682 ; U1.AD8@113.914,34.367 113.914,34.295 v2(114.63,33.579) ; SB5.1@122.139,54.197 123.952,52.384 123.952,49.124 v2(124.181,48.895)
  Mid-Layer 1 w0.152: v2(102.718,51.486) 102.718,52.299 103.226,52.807 104.8,52.807 105.994,51.613 114.99,51.613 117.944,48.659 122.522,48.659 122.778,48.915 124.16,48.915 v2(124.181,48.895) ; v2(114.63,33.579) 115.102,33.579 116.03,32.651 116.578,32.651 117.041,32.188 117.041,30.427 116.992,30.378 v1(116.992,29.87)
  Mid-Layer 2 w0.152: v1(103.276,29.032) 103.607,29.032 105.022,30.447 105.022,36.597 106.017,37.592 106.017,43.2 104.267,44.95 v1(104.267,44.958)
  Bottom Layer w0.152: v1(103.276,29.032) 103.97,29.032 104.211,28.792 110.022,28.792 110.402,29.171 110.419,29.171 110.882,29.635 116.757,29.635 v1(116.992,29.87)
P0.14: P24.4 SB6.1 U1.AC9 | length 84.1
  Top Layer w0.152: P24.4@97.472,50.8 101.461,50.8 102.553,51.892 v2(103.149,51.892) 103.353,51.689 103.353,49.468 104.572,48.249 v1(104.572,45.669) ; SB6.1@122.139,52.774 123.647,51.266 123.647,48.666 v2(123.8,48.514)
  Mid-Layer 1 w0.152: v2(103.149,51.892) 103.149,52.299 103.352,52.502 104.674,52.502 105.868,51.308 114.867,51.308 117.818,48.357 122.647,48.357 122.825,48.534 123.779,48.534 v2(123.8,48.514) ; v2(114.164,34.867) 114.164,34.8 114.512,34.451 114.512,34.201 114.747,33.966 115.142,33.966 116.155,32.953 116.703,32.953 117.343,32.313 117.343,30.699 117.704,30.338 v1(117.704,29.566)
  Mid-Layer 2 w0.152: v1(102.54,28.829) 102.868,28.501 103.507,28.501 104.978,29.972 104.978,29.976 105.324,30.322 105.324,36.471 106.32,37.467 106.32,43.921 v1(104.572,45.669)
  Bottom Layer w0.152: v1(102.54,28.829) 102.88,28.489 110.164,28.489 111.008,29.333 117.471,29.333 v1(117.704,29.566)
P0.15: P24.5 SB7.1 U1.AD10 | length 81.9
  Top Layer w0.152: P24.5@93.027,48.26 94.285,48.26 95.402,49.378 99.314,49.378 103.734,44.958 103.734,44.737 104.267,44.204 v1(104.267,44.196) 105.207,45.136 105.207,48.034 103.657,49.584 v2(103.657,52.095) ; U1.AD10@114.414,34.367 114.414,34.3 114.747,33.966 114.81,33.966 115.062,33.714 115.062,33.435 114.91,33.282 v2(114.91,33.147) ; SB7.1@122.139,51.352 123.342,50.149 123.342,48.209 v2(123.419,48.133)
  Mid-Layer 1 w0.152: v2(103.657,52.095) 104.649,52.095 105.742,51.003 114.744,51.003 117.693,48.054 122.773,48.054 122.871,48.153 123.398,48.153 v2(123.419,48.133) ; v2(114.91,33.147) 115.106,33.147 115.905,32.348 116.452,32.348 116.738,32.063 116.738,31.115 v1(116.434,30.81)
  Mid-Layer 2 w0.152: v1(103.556,30.302) 104.417,31.163 104.417,42.889 104.041,43.265 104.041,43.705 104.267,43.931 v1(104.267,44.196)
  Bottom Layer w0.152: v1(103.556,30.302) 104.462,29.396 109.772,29.396 110.615,30.24 116.183,30.24 116.434,30.49 v1(116.434,30.81)
P0.16: P24.6 SB8.1 U1.AC11 | length 85.2
  Top Layer w0.152: P24.6@97.472,48.26 100.011,48.26 103.429,44.842 103.429,44.28 104.224,43.485 v1(104.572,43.485) 104.572,43.746 105.504,44.679 105.504,48.158 103.962,49.7 103.962,51.486 v2(104.115,51.638) ; SB8.1@122.139,49.93 123.015,49.054 123.015,47.775 v2(123.038,47.752)
  Mid-Layer 1 w0.152: v2(104.115,51.638) 104.676,51.638 105.615,50.698 114.622,50.698 117.568,47.752 v2(123.038,47.752) ; v2(114.664,34.867) 114.664,34.935 114.997,35.269 117.33,35.269 117.382,35.216 118.128,35.216 118.277,35.067 121.31,32.034 v1(121.31,31.293)
  Mid-Layer 2 w0.152: v1(102.997,29.743) 103.89,29.743 104.719,30.573 104.719,43.337 v1(104.572,43.485)
  Bottom Layer w0.152: v1(102.997,29.743) 103.687,29.743 104.336,29.094 109.897,29.094 110.74,29.937 116.308,29.937 116.772,30.401 119.157,30.401 119.817,31.062 120.3,31.062 120.531,31.293 v1(121.31,31.293)
P0.17: SB13.1 SB23.1 U1.AD12 | length 16.6
  Top Layer w0.203: SB13.1@119.337,21.768 v1(119.634,21.768) 119.957,21.768
  Mid-Layer 1 w0.152: v2(114.914,34.367) 115.169,34.367 116.28,33.256 116.828,33.256 117.646,32.438 117.646,30.824 118.3,30.17 118.3,29.189 117.178,28.067 117.178,26.535 117.935,25.779 117.935,24.901 118.11,24.725 v1(118.11,23.647)
  Bottom Layer w0.152: v1(118.11,23.647) 118.11,23.292 v1(119.634,21.768)
P0.18/RESET: P18.10 P24.8 P25.10 SB42.2 SB44.2 SB45.2 SB56.1 U1.AC13 | length 124.3
  Top Layer w0.152: v1(62.272,25.155) 61.517,25.155 61.199,25.473 61.199,25.915 61.512,26.227 62.395,26.227 63.678,24.945 76.877,24.945 76.963,24.858 78.878,24.858 P18.10@80.01,25.99 80.01,26.717 81.94,28.647 81.94,32.41 81.534,32.816 80.645,32.816 80.01,33.452 P25.10@80.01,34.245 ; 86.589,20.683 86.668,20.683 87.884,20.683 ; v1(88.849,22.581) 87.884,21.615 87.884,20.683 ; 89.1,20.683 87.884,20.683 ; 89.408,20.683 89.716,20.683 ; v1(96.926,47.015) 97.472,46.469 P24.8@97.472,45.72 ; v1(105.918,24.003) 105.918,25.044 107.544,26.67 117.526,26.67 v2(117.627,26.772)
  Top Layer w0.203: 57.396,19.916 SB56.1@57.396,20.269
  Mid-Layer 1 w0.152: v2(115.164,34.867) 115.164,34.8 116.406,33.558 116.954,33.558 117.948,32.564 117.948,30.949 118.602,30.295 118.602,29.063 117.48,27.941 117.48,26.919 v2(117.627,26.772)
  Mid-Layer 2 w0.152: v1(94.869,25.324) 94.869,25.658 95.682,26.471 95.682,38.516 96.52,39.354 96.52,43.942 96.926,44.348 v1(96.926,47.015)
  Bottom Layer w0.152: v1@57.389,19.583 v1(57.389,19.658) 58.467,19.658 62.272,23.463 v1(62.272,25.155) ; v1(78.994,25.197) 79.934,24.257 84.01,24.257 86.322,21.946 87.856,21.946 88.67,22.76 ; v1(88.849,22.581) 88.67,22.76 ; v1(94.869,25.324) 94.64,25.552 93.539,25.552 92.774,24.787 90.697,24.787 88.67,22.76 ; v1@94.869,25.552 95.95,25.552 96.964,24.539 105.382,24.539 v1(105.918,24.003)
P0.19: SB11.1 SB21.1 U1.AC15 | length 28.7
  Top Layer w0.152: v1(105.004,24.003) 105.004,24.562 107.417,26.975 117.263,26.975 117.504,27.216 v2(117.881,27.216)
  Top Layer w0.203: 107.881,24.308 108.056,24.308 v1(108.204,24.308) SB11.1@108.501,24.308
  Mid-Layer 1 w0.152: v2(115.664,34.867) 115.664,34.8 116.603,33.86 117.079,33.86 118.25,32.689 118.25,31.074 118.905,30.42 118.905,28.938 117.991,28.024 117.991,27.325 v2(117.881,27.216)
  Bottom Layer w0.152: v1(105.004,24.003) 105.122,24.003 105.783,23.343 107.239,23.343 v1(108.204,24.308)
P0.20: SB12.1 SB22.1 U1.AD16 | length 21.3
  Top Layer w0.152: 107.881,25.578 108.204,25.578 ; SB12.1@108.501,25.578 108.204,25.578 ; U1.AD16@115.914,34.367 115.914,34.099 116.792,33.221 116.792,32.004 116.794,32.002 116.794,31.234 119.108,28.92 119.108,26.805 118.669,26.365 108.41,26.365 108.204,26.16 108.204,25.578
P0.21: SB14.1 SB24.1 U1.AC17 | length 14.9
  Top Layer w0.203: SB14.1@119.337,23.038 v1(119.634,23.038) 119.957,23.038
  Mid-Layer 1 w0.152: v2(116.164,34.867) 116.164,34.8 116.801,34.163 117.204,34.163 118.553,32.814 118.553,31.2 119.207,30.545 119.207,28.813 118.293,27.899 118.293,25.293 118.415,25.171 v1@118.44,25.197
  Bottom Layer w0.152: v1@118.415,25.171 118.415,24.257 v1(119.634,23.038)
  other v1: 118.466,25.171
